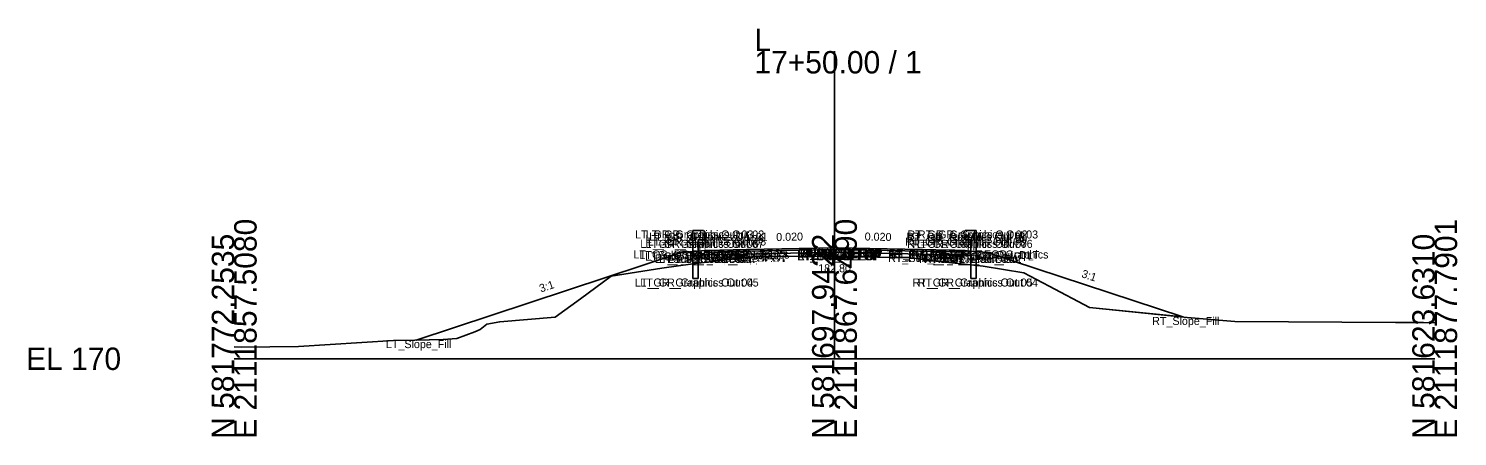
# Model space of a CAD drawing. Extents: x -486 to 1153, y -333 to 9539.
# Drawn here: x -25.7 to 152.8, y 7990.3 to 8041.2 of the extents above; entities that cross this region are included whole.
import ezdxf

# ---------------------------------------------------------------- set-up
doc = ezdxf.new("R2010")
doc.units = 0
for name, color, linetype in [('Default', 7, 'Continuous'), ('Exist Cross Section Cell', 7, 'Continuous'), ('Exist XS Ground Line', 7, 'Continuous'), ('Prop CMT Guardrail Graphics', 7, 'Continuous'), ('Prop CMT Pvmt Course 1', 7, 'Continuous'), ('Prop CMT Pvmt Course 2', 7, 'Continuous'), ('Prop CMT Pvmt Course 3', 7, 'Continuous'), ('Prop CMT Pvmt Surface', 7, 'Continuous'), ('Prop CMT Pvmt Surface Shoulder', 7, 'Continuous'), ('Prop CMT Shld Paved Course 1', 7, 'Continuous'), ('Prop CMT Shld Paved Course 2', 7, 'Continuous'), ('Prop CMT Shld Paved Course 3', 7, 'Continuous'), ('Prop CMT Slope Grass', 7, 'Continuous'), ('Prop CMT Subgrade Earthwork', 7, 'Continuous'), ('Prop XS Earthwork Shape', 7, 'Continuous'), ('Prop XS SE Text', 7, 'Continuous'), ('Prop XS Side Slope Text', 7, 'Continuous'), ('Scratch_Level_0', 7, 'Continuous')]:
    doc.layers.add(name, color=color, linetype=linetype)

msp = doc.modelspace()

# ---------------------------------------------------------------- linework, layer by layer
at = {"layer": 'Exist Cross Section Cell'}
for p, q in [((75, 8000), (75, 8038.42)), ((0, 8000), (75, 8000)), ((75, 8000), (150, 8000))]:
    msp.add_line(p, q, dxfattribs=at)
at = {"layer": 'Exist XS Ground Line'}
for p, q in [((57.32, 8011.85), (65.01, 8012.75)), ((65.01, 8012.75), (66.97, 8012.76)), ((66.97, 8012.76), (74.38, 8012.81)), ((74.38, 8012.81), (75, 8012.8)), ((75, 8012.8), (82.19, 8012.66)), ((82.19, 8012.66), (84.29, 8012.63)), ((84.29, 8012.63), (87.35, 8012.21)), ((47.12, 8010.31), (53.43, 8011.3)), ((53.43, 8011.3), (57.32, 8011.85)), ((87.35, 8012.21), (93.59, 8011.58)), ((93.59, 8011.58), (98.65, 8010.74)), ((43.29, 8007.49), (47.12, 8010.31)), ((98.65, 8010.74), (101.82, 8009.05)), ((101.82, 8009.05), (106.87, 8006.41)), ((40.11, 8005.18), (43.29, 8007.49)), ((106.87, 8006.41), (119.06, 8005.16)), ((30.08, 8003.35), (30.73, 8003.64)), ((30.73, 8003.64), (31.58, 8004.32)), ((31.58, 8004.32), (33.18, 8004.63)), ((33.18, 8004.63), (40.11, 8005.18)), ((119.06, 8005.16), (125.03, 8004.66)), ((125.03, 8004.66), (145.1, 8004.52)), ((145.1, 8004.52), (148.61, 8004.51)), ((148.61, 8004.51), (150, 8004.48)), ((8.04, 8001.53), (19.92, 8002.27)), ((19.92, 8002.27), (22.59, 8002.33)), ((22.59, 8002.33), (26.13, 8002.4)), ((26.13, 8002.4), (27.8, 8002.51)), ((27.8, 8002.51), (30.08, 8003.35)), ((0, 8001.51), (0.87, 8001.46)), ((0.87, 8001.46), (8.04, 8001.53))]:
    msp.add_line(p, q, dxfattribs=at)
at = {"layer": 'Prop CMT Guardrail Graphics'}
for points in [[(57.3, 8010.02), (57.3, 8016.02)], [(57.3, 8016.02), (58.63, 8016.02), (58.9, 8015.73)], [(58.9, 8015.14), (58.63, 8014.85), (57.96, 8014.85)], [(57.96, 8014.85), (57.96, 8010.02)], [(58.9, 8015.73), (58.63, 8015.44)], [(58.63, 8015.44), (58.9, 8015.14)], [(92.7, 8016.02), (91.37, 8016.02), (91.1, 8015.73)], [(91.1, 8015.73), (91.37, 8015.44)], [(91.37, 8015.44), (91.1, 8015.14)], [(91.1, 8015.14), (91.37, 8014.85), (92.04, 8014.85)], [(92.04, 8014.85), (92.04, 8010.02)], [(92.7, 8010.02), (92.7, 8016.02)], [(57.96, 8010.02), (57.3, 8010.02)], [(92.04, 8010.02), (92.7, 8010.02)]]:
    msp.add_lwpolyline(points, dxfattribs=at)
at = {"layer": 'Prop CMT Pvmt Course 1'}
for points in [[(75, 8013.85), (64, 8013.63)], [(64, 8013.42), (75, 8013.64)], [(64, 8013.63), (64, 8013.42)], [(75, 8013.64), (75, 8013.85)], [(75, 8013.85), (86, 8013.63)], [(75, 8013.64), (75, 8013.85)], [(86, 8013.42), (75, 8013.64)], [(86, 8013.63), (86, 8013.42)]]:
    msp.add_lwpolyline(points, dxfattribs=at)
msp.add_lwpolyline([(75, 8013.64), (75, 8013.72), (75, 8013.72), (75, 8013.64)], close=True, dxfattribs=at)
msp.add_lwpolyline([(75, 8013.64), (75, 8013.72), (75, 8013.72), (75, 8013.64)], close=True, dxfattribs=at)
at = {"layer": 'Prop CMT Pvmt Course 2'}
for points in [[(75, 8013.64), (64, 8013.42)], [(64, 8013.42), (64, 8013.08)], [(64, 8013.08), (75, 8013.3)], [(75, 8013.3), (75, 8013.64)], [(75, 8013.3), (75, 8013.64)], [(75, 8013.64), (86, 8013.42)], [(86, 8013.08), (75, 8013.3)], [(86, 8013.42), (86, 8013.08)]]:
    msp.add_lwpolyline(points, dxfattribs=at)
at = {"layer": 'Prop CMT Pvmt Course 3'}
for points in [[(75, 8013.3), (64, 8013.08)], [(64, 8013.08), (64, 8013.08)], [(75, 8013.3), (75, 8013.3)], [(75, 8013.3), (86, 8013.08)], [(75, 8013.3), (75, 8013.3)], [(86, 8013.08), (86, 8013.08)]]:
    msp.add_lwpolyline(points, dxfattribs=at)
at = {"layer": 'Prop CMT Pvmt Surface'}
for points in [[(75, 8013.85), (64, 8013.63)], [(75, 8013.85), (86, 8013.63)]]:
    msp.add_lwpolyline(points, dxfattribs=at)
at = {"layer": 'Prop CMT Pvmt Surface Shoulder'}
for points in [[(64, 8013.63), (59, 8013.53)], [(86, 8013.63), (91, 8013.53)]]:
    msp.add_lwpolyline(points, dxfattribs=at)
at = {"layer": 'Prop CMT Shld Paved Course 1'}
for points in [[(64, 8013.63), (59, 8013.53), (58.79, 8013.31)], [(58.79, 8013.31), (64, 8013.42)], [(64, 8013.42), (64, 8013.63)], [(86, 8013.63), (91, 8013.53), (91.21, 8013.31)], [(86, 8013.42), (86, 8013.63)], [(91.21, 8013.31), (86, 8013.42)]]:
    msp.add_lwpolyline(points, dxfattribs=at)
at = {"layer": 'Prop CMT Shld Paved Course 2'}
for points in [[(64, 8013.42), (58.79, 8013.31), (58.45, 8012.97)], [(58.45, 8012.97), (64, 8013.08)], [(64, 8013.08), (64, 8013.42)], [(86, 8013.42), (91.21, 8013.31), (91.55, 8012.97)], [(86, 8013.08), (86, 8013.42)], [(91.55, 8012.97), (86, 8013.08)]]:
    msp.add_lwpolyline(points, dxfattribs=at)
at = {"layer": 'Prop CMT Shld Paved Course 3'}
for points in [[(64, 8013.08), (58.45, 8012.97)], [(58.45, 8012.97), (58.45, 8012.97), (58.45, 8012.97)], [(64, 8013.08), (64, 8013.08)], [(86, 8013.08), (91.55, 8012.97)], [(86, 8013.08), (86, 8013.08)], [(91.55, 8012.97), (91.55, 8012.97), (91.55, 8012.97)]]:
    msp.add_lwpolyline(points, dxfattribs=at)
at = {"layer": 'Prop CMT Slope Grass'}
for points in [[(55.9, 8013.28), (22.72, 8002.33)], [(58.9, 8013.52), (55.9, 8013.28)], [(59, 8013.53), (58.9, 8013.52)], [(91, 8013.53), (91.1, 8013.52)], [(91.1, 8013.52), (94.1, 8013.28)], [(94.1, 8013.28), (118.52, 8005.22)]]:
    msp.add_lwpolyline(points, dxfattribs=at)
at = {"layer": 'Prop CMT Subgrade Earthwork'}
for points in [[(58.45, 8012.97), (57.98, 8013.44)], [(64, 8013.08), (58.45, 8012.97)], [(75, 8013.3), (64, 8013.08)], [(75, 8013.3), (86, 8013.08)], [(86, 8013.08), (91.55, 8012.97)], [(91.55, 8012.97), (92.02, 8013.44)]]:
    msp.add_lwpolyline(points, dxfattribs=at)
at = {"layer": 'Prop XS Earthwork Shape'}
msp.add_lwpolyline([(66.97, 8012.76), (74.38, 8012.81), (75, 8012.8), (82.19, 8012.66), (84.29, 8012.63), (87.35, 8012.21), (93.59, 8011.58), (98.65, 8010.74), (101.82, 8009.05), (106.87, 8006.41), (118.52, 8005.22), (94.1, 8013.28), (92.02, 8013.44), (91.55, 8012.97), (86, 8013.08), (75, 8013.3), (64, 8013.08), (58.45, 8012.97), (57.98, 8013.44), (55.9, 8013.28), (22.72, 8002.33), (26.13, 8002.4), (27.8, 8002.51), (30.08, 8003.35), (30.73, 8003.64), (31.58, 8004.32), (33.18, 8004.63), (40.11, 8005.18), (43.29, 8007.49), (47.12, 8010.31), (53.43, 8011.3), (57.32, 8011.85), (65.01, 8012.75)], close=True, dxfattribs=at)

# ---------------------------------------------------------------- texts
at = {"layer": 'Default'}
for s, height, p in [('182.80', 1, (72.97, 8010.8)), ('-', 0.0001, (0, 8000))]:
    msp.add_text(s, height=height, dxfattribs=at).set_placement(p)
at = {"layer": 'Exist Cross Section Cell'}
for s, p in [('L', (65, 8038.42)), ('17+50.00 / 1', (65, 8035.62)), ('EL 170', (-26, 7998.6))]:
    msp.add_text(s, height=2.8, dxfattribs=at).set_placement(p)
for s, p in [('E 2111857.5080', (2.8, 7990)), ('E 2111867.6490', (77.8, 7990)), ('E 2111877.7901', (152.8, 7990)), ('N 581772.2535', (0, 7990)), ('N 581697.9422', (75, 7990)), ('N 581623.6310', (150, 7990))]:
    msp.add_text(s, height=2.8, rotation=90, dxfattribs=at).set_placement(p)
at = {"layer": 'Prop XS SE Text'}
for rotation, p in [(1.1458, (67.73, 8014.7)), (358.8542, (78.77, 8014.77))]:
    msp.add_text('0.020', height=1, rotation=rotation, dxfattribs=at).set_placement(p)
at = {"layer": 'Prop XS Side Slope Text'}
for rotation, p in [(341.7371, (105.79, 8010.21)), (18.2629, (38.32, 8008.27))]:
    msp.add_text('3:1', height=1, rotation=rotation, dxfattribs=at).set_placement(p)
at = {"layer": 'Scratch_Level_0'}
for s, p in [('LT_GR_Graphics Out 03', (50.08, 8015.02)), ('LT_GR_Graphics Out 06', (50.74, 8013.85)), ('LT_GR_Graphics Out 07', (51.39, 8013.85)), ('LT_GR_Graphics Out 09', (51.4, 8014.44)), ('LT_GR_Graphics Out 02', (51.43, 8015.02)), ('LT_GR_Graphics Out 08', (51.67, 8014.14)), ('LT_GR_Graphics Out 01', (51.85, 8014.73)), ('RT_GR_Graphics Out 08', (83.81, 8014.14)), ('RT_GR_Graphics Out 01', (83.99, 8014.73)), ('RT_GR_Graphics Out 07', (84.07, 8013.85)), ('RT_GR_Graphics Out 09', (84.09, 8014.44)), ('RT_GR_Graphics Out 02', (84.11, 8015.02)), ('RT_GR_Graphics Out 06', (84.75, 8013.85)), ('RT_GR_Graphics Out 03', (85.43, 8015.02)), ('LT_GS_OS_GR_Face_Graphics', (49.9, 8012.52)), ('LT_Sub_Trench_Out_DLT', (50.63, 8012.44)), ('LT_GS_OS_CTL', (51.36, 8012.28)), ('LT_Sub_Trench_Out', (52.56, 8011.97)), ('LT_PS3_Shelf_Out', (53.1, 8011.97)), ('LT_PS3_OEOP', (54.23, 8011.97)), ('LT_PS2_OEOP', (54.57, 8012.31)), ('LT_PS1_OEOP', (54.91, 8012.53)), ('LT_PV2_OEOT', (59.75, 8012.42)), ('LT_PV3_OEOT', (59.75, 8012.08)), ('LT_Sub_OEOT', (59.77, 8012.08)), ('LT_PV1_OEOT', (59.87, 8012.63)), ('RT_PV2_OEEOP', (70.33, 8012.64)), ('RT_PV3_OEEOP', (70.33, 8012.3)), ('RT_Sub_OEEOP', (70.36, 8012.3)), ('LT_PV2_OEEOP', (70.39, 8012.64)), ('LT_PV3_OEEOP', (70.39, 8012.3)), ('LT_Sub_OEEOP', (70.42, 8012.3)), ('RT_PV1_OEEOP', (70.45, 8012.72)), ('LT_PV1_OEEOP', (70.51, 8012.72)), ('RT_PV2_IEEOP', (70.71, 8012.64)), ('LT_PV2_IEEOP', (70.77, 8012.64)), ('RT_PV1_IEEOP', (70.83, 8012.72)), ('LT_PV1_IEEOP', (70.89, 8012.72)), ('PV2_PGL', (72.35, 8012.64)), ('PV1_PGL', (72.47, 8012.85)), ('RT_PV2_OEOT', (81.69, 8012.42)), ('RT_PV3_OEOT', (81.69, 8012.08)), ('RT_Sub_OEOT', (81.71, 8012.08)), ('RT_PV1_OEOT', (81.81, 8012.63)), ('RT_GS_OS_GR_Face_Graphics', (82.04, 8012.52)), ('RT_Sub_Trench_Out_DLT', (84.61, 8012.44)), ('RT_Sub_Trench_Out', (85.6, 8011.97)), ('RT_PS3_Shelf_Out', (86.15, 8011.97)), ('RT_PS1_OEOP', (86.85, 8012.53)), ('RT_PS2_OEOP', (86.94, 8012.31)), ('RT_PS3_OEOP', (87.28, 8011.97)), ('RT_GS_OS_CTL', (89.5, 8012.28)), ('LT_GR_Graphics Out 04', (50.07, 8009.02)), ('LT_GR_Graphics Out 05', (50.74, 8009.02)), ('RT_GR_Graphics Out 05', (84.76, 8009.02)), ('RT_GR_Graphics Out 04', (85.41, 8009.02)), ('RT_Slope_Fill', (114.7, 8004.22)), ('LT_Slope_Fill', (18.96, 8001.33))]:
    msp.add_text(s, height=1, dxfattribs=at).set_placement(p)

doc.saveas('drawing.dxf')
